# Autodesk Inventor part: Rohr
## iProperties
Created: 2005-12
Part Number: Rohr
Document SubType Name: Modeling
Designer: Sascha
Manufacturer: Standard
Standards Organization: Custom
Author: Sascha
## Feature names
1. Extrusion1
2. Extrusion2
3. Extrusion3
4. Fase1 [Chamfer]
5. Fase2 [Chamfer]
6. Bohrung1 [Hole]
7. Runde Anordnung1 [Circular Pattern]
8. Bohrung2 [Hole]
9. Runde Anordnung2 [Circular Pattern]
10. Rechteckige Anordnung1 [Rectangular Pattern]
11. Bohrung3 [Hole]
12. Runde Anordnung3 [Circular Pattern]
13. Rechteckige Anordnung2 [Rectangular Pattern]
